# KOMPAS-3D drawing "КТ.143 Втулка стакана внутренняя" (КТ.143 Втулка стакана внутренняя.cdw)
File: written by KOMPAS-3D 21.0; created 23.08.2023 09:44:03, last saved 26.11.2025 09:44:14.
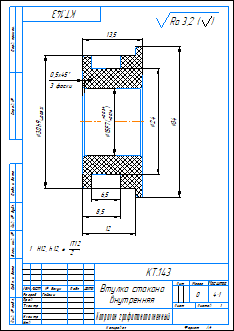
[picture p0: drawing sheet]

Sheet 1: A4, portrait

Document properties: Автор: Марсель; Организация: User; Полное имя файла: C:\Users\User\Desktop\Pelorus PRO доработки\ЗАФИКСИРОВАЛИ\Втулка стакана внутренняя\КТ.143 Втулка стакана внутренняя.cdw; Знак неуказанной шероховатости: 4; Параметр неуказанной шероховатости: Ra 3,2

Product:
- Part/product: КТ.143 Втулка стакана внутренняя
    Комментарий: User

Title block, sheet 1: Наименование: Втулка стакана / внутренняя; designation: КТ.143; Материал: Капролон графитонаполненный; Масса: 0; Количество листов документа: 1; Форматы листов документа: A4; stored path: C:\Marsel\маршрутная и тит.л\Чертеж.cdw; Разработал: Гайсин

Views: Вид 1, Местный разрез 1, Слева
Referenced files in C:\Users\User\Desktop\Pelorus PRO доработки\ЗАФИКСИРОВАЛИ\Втулка стакана внутренняя\: КТ.143 Втулка стакана внутренняя.m3d, КТ.143 Втулка стакана внутренняя_1.m3d
Referenced files in C:\Marsel\KazanTarget\Новые проекты\ВАРИАНТЫ СКЛАДЫВАНИЯ\Втулка 15\: Втулка 15.m3d
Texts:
  КТ.143 Втулка стакана внутренняя
  Ra 3,2
  Ra 3,2 ( )
Dimensions and other numbers on the sheet: 13,5; 34; 30; 8,5; 12; 6,5; 0,5; 3 фаски; 15; 24; 4:1; 1; 0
